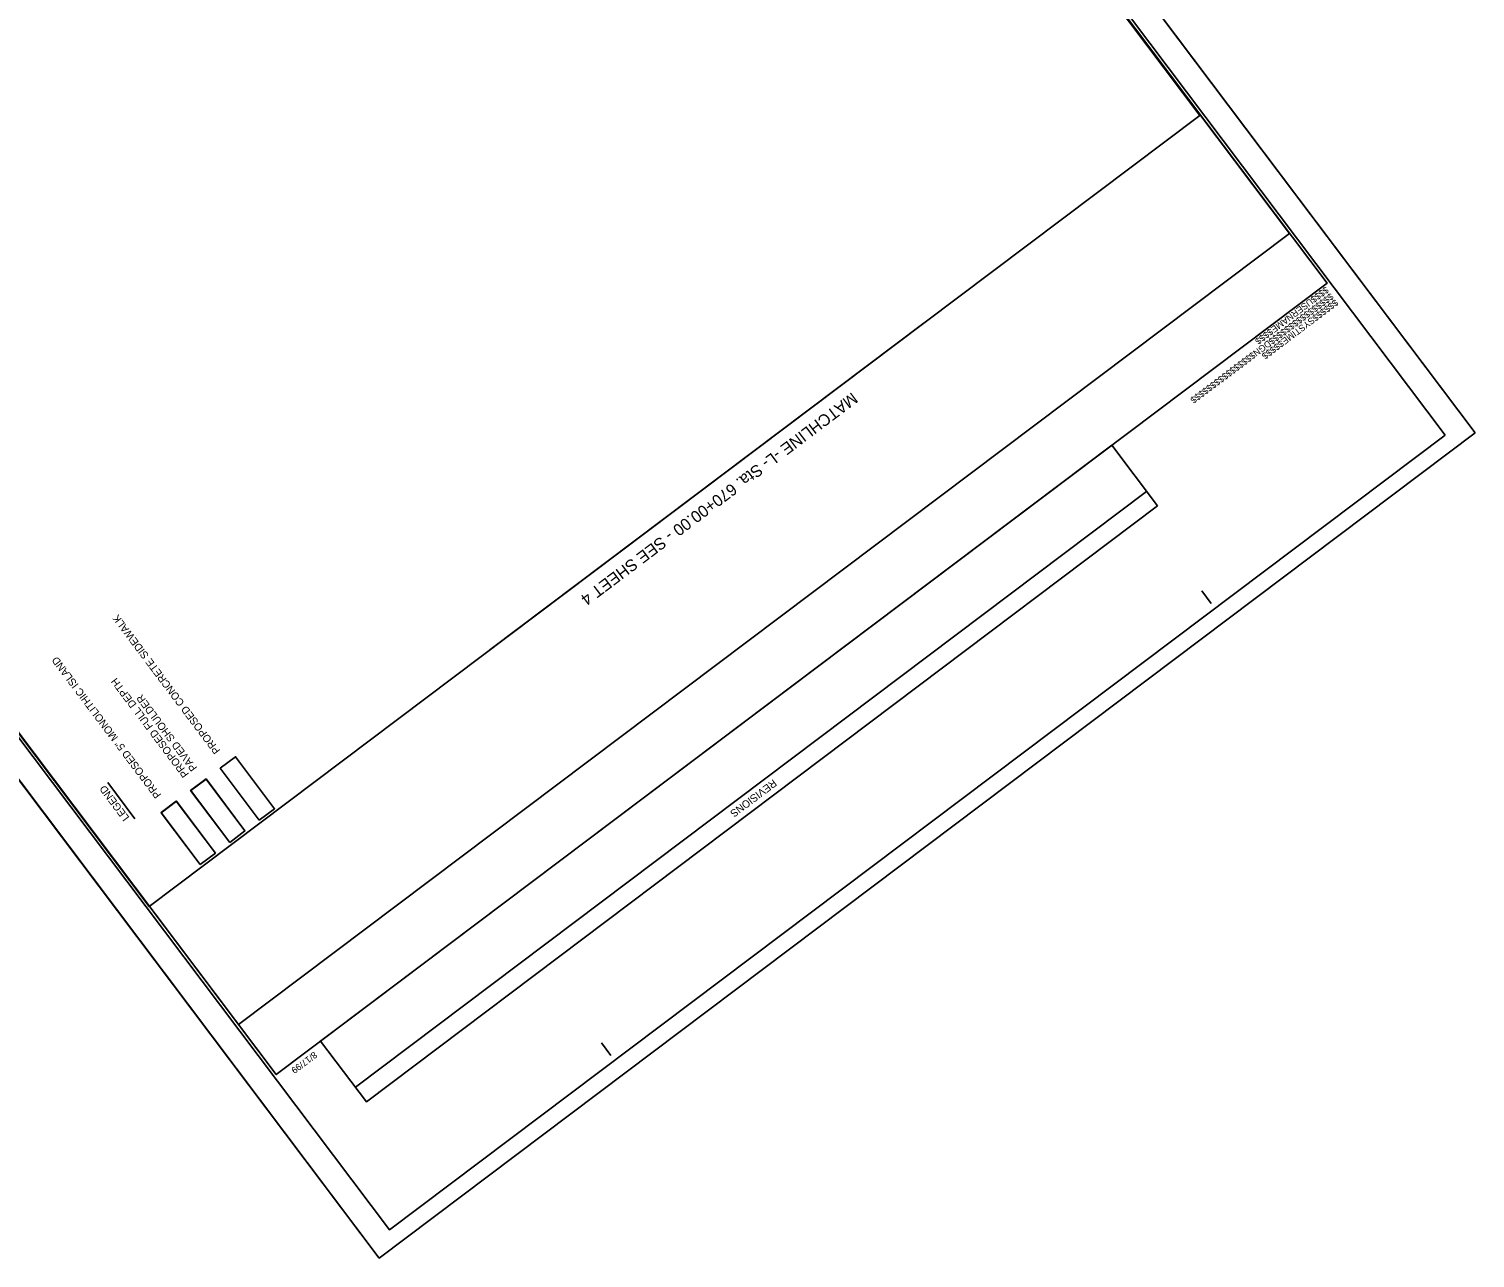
# Model space of a CAD drawing. Extents: x 1262337 to 1264328, y 775525 to 777528.
# Drawn here: x 1263174 to 1264328, y 775525 to 776506 of the extents above; entities that cross this region are included whole.
import ezdxf

# ---------------------------------------------------------------- set-up
doc = ezdxf.new("R2010")
doc.units = 0
for name, color, linetype in [('Matchline', 7, 'Continuous'), ('Old_Level_1', 7, 'Continuous'), ('Prop Shade Light', 7, 'Continuous'), ('Prop Shade Medium', 7, 'Continuous'), ('Sheet Block Revision CELL', 7, 'Continuous'), ('Sheet Clip Boundary CELL', 7, 'Continuous'), ('Sheet Cutting Line CELL', 7, 'Continuous'), ('Sheet Layout Plan Border', 7, 'Continuous'), ('Sheet Plan CELL', 7, 'Continuous'), ('Sheet Plan Layout CELL', 7, 'Continuous'), ('Sheet Plot Border Inside CELL', 7, 'Continuous'), ('Sheet Plot Border Outside CELL', 7, 'Continuous')]:
    doc.layers.add(name, color=color, linetype=linetype)

msp = doc.modelspace()

# ---------------------------------------------------------------- linework, layer by layer
at = {"layer": 'Matchline'}
msp.add_line((1263542, 776010.3), (1263888.7, 776271.4), dxfattribs=at)
at = {"layer": 'Prop Shade Light'}
msp.add_lwpolyline([(1263334.4, 775856.5), (1263346.6, 775865.7), (1263315.5, 775907.1), (1263303.3, 775897.9)], close=True, dxfattribs=at)
at = {"layer": 'Prop Shade Medium'}
msp.add_lwpolyline([(1263358, 775874.2), (1263370.2, 775883.4), (1263339.1, 775924.9), (1263326.9, 775915.7), (1263358, 775874.2)], dxfattribs=at)
msp.add_lwpolyline([(1263310.8, 775838.8), (1263323, 775848), (1263291.9, 775889.4), (1263279.7, 775880.2)], close=True, dxfattribs=at)
at = {"layer": 'Sheet Block Revision CELL'}
msp.add_line((1264066.2, 776136.8), (1263434.7, 775661.1), dxfattribs=at)
msp.add_lwpolyline([(1264075, 776125.2), (1263443.5, 775649.5), (1263407, 775697.9), (1264038.6, 776173.6)], close=True, dxfattribs=at)
at = {"layer": 'Sheet Clip Boundary CELL'}
msp.add_lwpolyline([(1263888.5, 776271.1), (1264108.8, 776437), (1263657.3, 777036.5), (1263449, 777317.2), (1262881.7, 776889.9), (1262608.3, 776683.9), (1263270.1, 775805.3)], close=True, dxfattribs=at)
at = {"layer": 'Sheet Cutting Line CELL'}
for p, q in [((1264328.5, 776183.5), (1263315.6, 777528.2)), ((1262440.9, 776869.4), (1263453.8, 775524.7)), ((1263453.8, 775524.7), (1264328.5, 776183.5))]:
    msp.add_line(p, q, dxfattribs=at)
at = {"layer": 'Sheet Layout Plan Border'}
msp.add_lwpolyline([(1264180.2, 776342.8), (1263337.9, 777461.1), (1262668.1, 776956.6), (1262782, 776805.5), (1262613.1, 776678.2), (1263341.5, 775711.1)], close=True, dxfattribs=at)
at = {"layer": 'Sheet Plan CELL'}
for p, q in [((1264210.3, 776302.9), (1264210.3, 776302.9)), ((1264117.9, 776047.4), (1264110.4, 776057.4)), ((1263258.8, 775875.4), (1263237.1, 775904.4)), ((1263638.7, 775686.4), (1263631.1, 775696.4)), ((1263371.6, 775671.2), (1263371.6, 775671.2))]:
    msp.add_line(p, q, dxfattribs=at)
for points in [[(1262469.1, 776869.4), (1263371.6, 775671.2), (1264210.3, 776302.9), (1263307.8, 777501.1)], [(1263358, 775874.2), (1263370.2, 775883.4), (1263339.1, 775924.9), (1263326.9, 775915.7)], [(1263334.4, 775856.5), (1263346.6, 775865.7), (1263315.5, 775907.2), (1263303.2, 775898)], [(1263310.8, 775838.8), (1263323, 775848), (1263291.8, 775889.5), (1263279.6, 775880.3)]]:
    msp.add_lwpolyline(points, close=True, dxfattribs=at)
at = {"layer": 'Sheet Plan Layout CELL'}
msp.add_lwpolyline([(1263371.6, 775671.2), (1264210.3, 776302.9), (1263307.8, 777501.1), (1262638.1, 776996.6), (1262782, 776805.5), (1262613.1, 776678.2)], close=True, dxfattribs=at)
at = {"layer": 'Sheet Plot Border Inside CELL'}
msp.add_lwpolyline([(1264304.7, 776181.8), (1263302.3, 777512.5), (1262459.6, 776877.8), (1263462, 775547.1)], close=True, dxfattribs=at)
at = {"layer": 'Sheet Plot Border Outside CELL'}
msp.add_lwpolyline([(1264328.5, 776183.5), (1263315.6, 777528.2), (1262440.9, 776869.4), (1263453.8, 775524.7)], close=True, dxfattribs=at)

# ---------------------------------------------------------------- texts
at = {"layer": 'Matchline'}
msp.add_text('MATCHLINE -L- Sta. 670+00.00 - SEE SHEET 4', height=9.375, rotation=216.9874, dxfattribs=at).set_placement((1263831.1, 776216.3))
at = {"layer": 'Old_Level_1'}
for s, p in [('PROPOSED CONCRETE SIDEWALK', (1263327.2, 775929.9)), ('PROPOSED 5" MONOLITHIC ISLAND', (1263280, 775894.5)), ('PROPOSED FULL DEPTH', (1263302.1, 775911.1)), ('PAVED SHOULDER', (1263308.7, 775916.1)), ('LEGEND', (1263254.6, 775876.4))]:
    msp.add_text(s, height=6, rotation=126.8862, dxfattribs=at).set_placement(p)
at = {"layer": 'Sheet Block Revision CELL'}
msp.add_text('REVISIONS', height=6, rotation=216.9874, dxfattribs=at).set_placement((1263768.2, 775907.3))
at = {"layer": 'Sheet Plan CELL'}
for s, p in [('$$$$USERNAME$$$$', (1264209.1, 776300.6)), ('$$$$$$$$$$$$$$$$DGN$$$$$$$$$$$$$$$$', (1264213, 776295.4)), ('$$$$$$SYSTIME$$$$$', (1264216.7, 776290.5)), ('8/17/99', (1263401.7, 775689.8))]:
    msp.add_text(s, height=5.25, rotation=216.9874, dxfattribs=at).set_placement(p)

doc.saveas('drawing.dxf')
